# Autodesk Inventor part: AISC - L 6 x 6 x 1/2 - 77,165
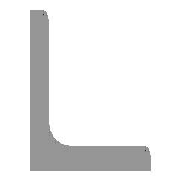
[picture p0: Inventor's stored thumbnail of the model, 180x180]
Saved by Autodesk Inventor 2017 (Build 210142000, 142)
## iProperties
Created: 2016-02
Part Number: AISC - L 6 x 6 x 1/2 - 77,165
Material: Stal, miękka
Description: Kątownik
Document SubType Name: Modeling
Standard: ANSI
Designer: X
Standards Organization: ANSI
Language: pl-PL
Size Designation: L 6 x 6 x 1/2
Categories: <MemberInstance><Categories><Category DisplayName="Kształtowniki konstrukcyjne" InternalName="089c4875-fa83-4c05-b084-43b9cc11f5ed" Mnemonic="GRDR"><CategoryPar
Stock Number: L 6 x 6 x 1/2
Density: 7.85 g/cm^3
Appearance: Częściowo polerowana
_CCFamilyMember: 47
_CCFamilyDisplayName: ANSI L (Kątownik równoramienny) - Kątownik — Rozmiary w nawiasach zostały wycofane
_FrameMemberDoc: Frame Member File
_Version: 15.0.0
_GetPNFromCC: 1
G_L: 1960,000 mm
G_W: 152,400 mm
G_H: 152,400 mm
IsCustomPart: 1
Author: X
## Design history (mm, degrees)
node "Płaszczyzna początkowa"
node "Płaszczyzna końcowa"
sketch "Szkic"
  geometry: L1 (152.4, 0)-(0, 0); L2 (0, 0)-(0, 152.4); L3 (0, 152.4)-(6.35, 152.4); L4 (12.7, 146.05)-(12.7, 25.4); L5 (25.4, 12.7)-(146.05, 12.7); L6 (152.4, 6.35)-(152.4, 0); L7 (0, -11.041)-(0, 31.538); L8 (-11.041, 0)-(31.538, 0); L9 (0, 186.666)-(0, -43.993) reference; L10 (-43.993, 0)-(186.666, 0) reference; A1 r 12.7 centre (25.4, 25.4) between (12.7, 25.4) and (25.4, 12.7); A2 r 6.35 centre (6.35, 146.05) between (12.7, 146.05) and (6.35, 152.4); A3 r 6.35 centre (146.05, 6.35) between (152.4, 6.35) and (146.05, 12.7); 3 further points
  constraints: 16 end point, 6 point on circle, 6 point on line, 6 tangent, 4 parallel, 3 centre point, 2 collinear, 1 equal radius, 1 horizontal, 1 perpendicular
  dimensions: "d0" = 152.4 distance between parallel lines of L6 L2 (= G_H); "d1" = 152.4 distance between parallel lines of L3 L1 (= G_H); "d2" = 12.7 distance between parallel lines of L2 L4 (= G_T); "d3" = 12.7 distance between parallel lines of L1 L5 (= G_T); "d10" = 0 distance between parallel lines of L7 L2 (computed from ex); "d11" = 0 distance between parallel lines of L8 L1 (computed from d10); "d14" = 12.7 radius of A1 (= G_IR); "d15" = 6.35 radius of A2 (= G_ER)
extrude "Bryła" new body sketch "Szkic" stored distance "d4" = 1960 (= G_L); taper "d5" = 0 deg
node "Driven Length"
  sketch "Sketch3"
    geometry: L1 (0, 0)-(10, 0) reference
    constraints: 2 end point, 1 horizontal
  workplane "Work Plane3"
  sketch "Sketch4"
    geometry: L1 (-2, 0)-(12, 0) reference; L2 (-2, 1960)-(12, 1960) reference
    dimensions: "d17" = 1960 distance between parallel lines of L1 L2 (derived)
body "Solid1"
other parameters: "G_H" = 152.4 [user parameter; used in 2 equation terms], "G_T" = 12.7 [user parameter; used in 2 equation terms], "G_ER" = 6.35 [user parameter; used in 1 equation term], "G_IR" = 12.7 [user parameter; used in 1 equation term], "G_L" = 1960 (= d17) [user parameter; used in 1 equation term], "ex" = 0 [user parameter; used in 1 equation term], "G_OFFSET_START" = 0 [user parameter; used in 1 equation term], "G_OFFSET_END" = 0 [user parameter; used in 1 equation term], "d12" = 0 (computed from G_OFFSET_START), "d16" = 90 deg, "MAS" = 2.9168 [user parameter]
